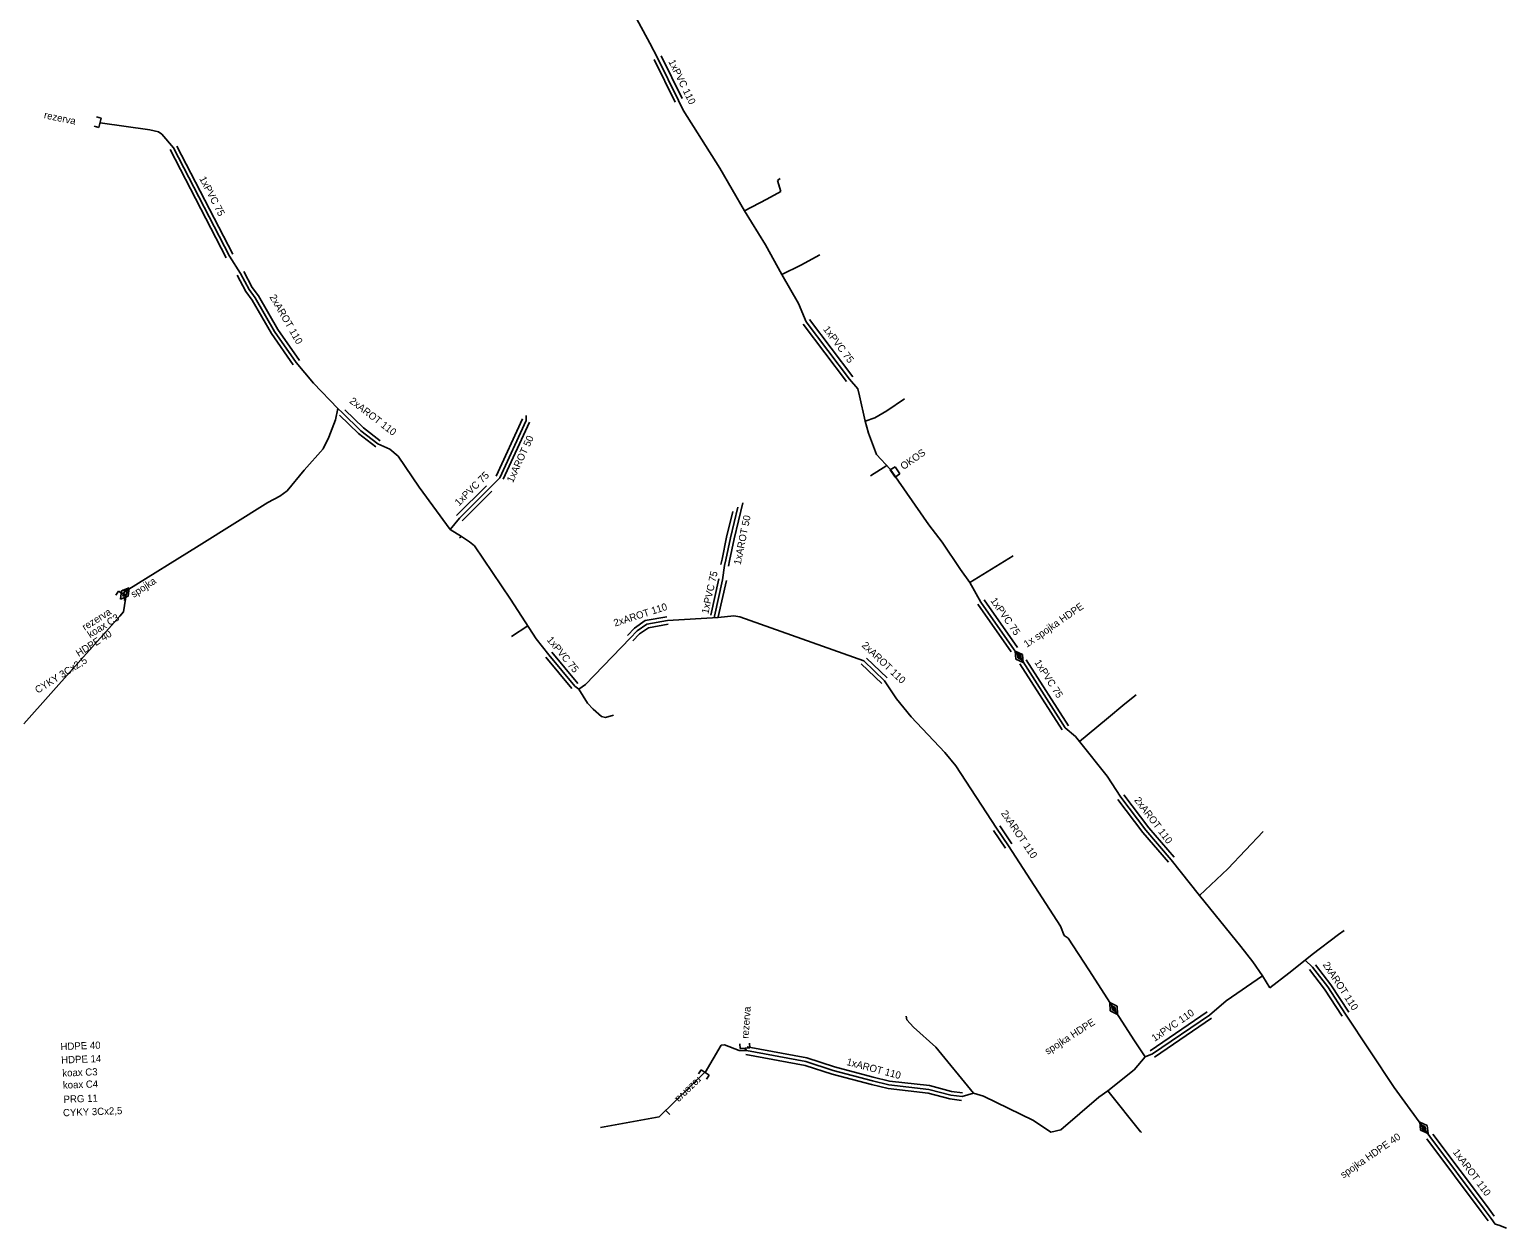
# Model space of a CAD drawing. Extents: x -651943 to -618711, y -1138561 to -1100552.
# Drawn here: x -649090.5 to -648936.6, y -1111816.6 to -1111691.7 of the extents above; entities that cross this region are included whole.
import ezdxf

# ---------------------------------------------------------------- set-up
doc = ezdxf.new("R2010")
doc.units = 0
doc.layers.add('KT trasa', color=7, linetype='Continuous')
doc.layers.add('KT zařízení', color=7, linetype='Continuous')

# ---------------------------------------------------------------- blocks, each defined once
blk = doc.blocks.new('TVREZ')
at = {"layer": 'KT zařízení'}
for p, q in [((-0.05, 0.05), (0, 0.05)), ((0, -0.05), (0, 0.05)), ((-0.05, -0.05), (0, -0.05))]:
    blk.add_line(p, q, dxfattribs=at)
blk = doc.blocks.new('TVSPO_1')
at = {"layer": 'KT zařízení'}
for p, q in [((-0.074, 0.002), (0, 0.044)), ((-0.001, -0.041), (-0.074, 0.002)), ((-0.035, 0), (0, 0.02)), ((0.073, 0.001), (-0.001, -0.041)), ((0, 0.044), (0.073, 0.001)), ((0, 0.02), (0.035, 0)), ((0.035, 0), (0, -0.02)), ((0, -0.02), (-0.035, 0))]:
    blk.add_line(p, q, dxfattribs=at)
blk = doc.blocks.new('POINT_DISPLAY')
blk.add_line((0, 0), (0, 0))

msp = doc.modelspace()

# ---------------------------------------------------------------- linework, layer by layer
at = {"layer": 'KT trasa'}
for p, q in [((-649027.47, -1111690.19), (-649025.84, -1111693.13)), ((-649025.84, -1111693.13), (-649025.05, -1111694.65)), ((-649025.05, -1111694.65), (-649022.86, -1111699.1)), ((-649022.86, -1111699.1), (-649022.39, -1111700.14)), ((-649022.39, -1111700.14), (-649018.57, -1111706.18)), ((-649083.16, -1111701.43), (-649077.98, -1111702.18)), ((-649077.98, -1111702.18), (-649077.08, -1111702.39)), ((-649077.08, -1111702.39), (-649076.72, -1111702.62)), ((-649076.72, -1111702.62), (-649075.51, -1111704.06)), ((-649069.67, -1111715.33), (-649075.51, -1111704.06)), ((-649018.57, -1111706.18), (-649015.98, -1111710.61)), ((-649012.56, -1111707.46), (-649012.27, -1111707.25)), ((-649012.2, -1111708.59), (-649012.56, -1111707.46)), ((-649015.98, -1111710.61), (-649013.67, -1111709.4)), ((-649013.67, -1111709.4), (-649012.2, -1111708.59)), ((-649015.98, -1111710.61), (-649013.81, -1111714.17)), ((-649013.81, -1111714.17), (-649012.08, -1111717.25)), ((-649069.67, -1111715.33), (-649068.53, -1111717.15)), ((-649010.1, -1111716.28), (-649008.14, -1111715.21)), ((-649068.53, -1111717.15), (-649067.63, -1111718.82)), ((-649012.08, -1111717.25), (-649010.1, -1111716.28)), ((-649012.08, -1111717.25), (-649010.37, -1111720.28)), ((-649067.63, -1111718.82), (-649066.98, -1111719.7)), ((-649064.96, -1111723.2), (-649066.98, -1111719.7)), ((-649010.37, -1111720.28), (-649009.55, -1111722.19)), ((-649009.55, -1111722.19), (-649005.03, -1111728.17)), ((-649062.7, -1111726.44), (-649064.96, -1111723.2)), ((-649060.9, -1111728.59), (-649062.7, -1111726.44)), ((-649005.03, -1111728.17), (-649004.16, -1111729.19)), ((-649058.38, -1111731.23), (-649060.9, -1111728.59)), ((-649004.16, -1111729.19), (-649004.01, -1111729.92)), ((-649004.01, -1111729.92), (-649003.4, -1111732.54)), ((-649058.38, -1111731.23), (-649058.63, -1111732.39)), ((-649057.92, -1111731.64), (-649058.38, -1111731.23)), ((-649002.4, -1111732.21), (-649001.14, -1111731.47)), ((-649001.14, -1111731.47), (-648999.31, -1111730.23)), ((-649058.63, -1111732.39), (-649059.3, -1111734.21)), ((-649055.96, -1111733.54), (-649057.92, -1111731.64)), ((-649041.5, -1111738.44), (-649038.75, -1111732.48)), ((-649038.75, -1111732.48), (-649038.73, -1111731.97)), ((-649003.4, -1111732.54), (-649002.4, -1111732.21)), ((-649003.4, -1111732.54), (-649003.07, -1111733.81)), ((-649059.3, -1111734.21), (-649059.91, -1111735.42)), ((-649054.19, -1111734.9), (-649055.96, -1111733.54)), ((-649003.07, -1111733.81), (-649002.23, -1111736.01)), ((-649059.91, -1111735.42), (-649061.9, -1111737.65)), ((-649052.94, -1111735.48), (-649054.19, -1111734.9)), ((-649052.09, -1111736.19), (-649052.94, -1111735.48)), ((-649049.9, -1111739.43), (-649052.09, -1111736.19)), ((-649061.9, -1111737.65), (-649063.65, -1111739.8)), ((-649002.84, -1111738.24), (-649001.16, -1111737.17)), ((-649042.59, -1111739.58), (-649041.5, -1111738.44)), ((-649064.41, -1111740.37), (-649065.68, -1111741.04)), ((-649063.65, -1111739.8), (-649064.41, -1111740.37)), ((-649046.66, -1111743.83), (-649049.9, -1111739.43)), ((-649045.71, -1111742.66), (-649042.59, -1111739.58)), ((-649065.68, -1111741.04), (-649072.81, -1111745.52)), ((-649017.46, -1111744.72), (-649016.68, -1111741.51)), ((-649046.66, -1111743.83), (-649045.71, -1111742.66)), ((-649045.5, -1111744.58), (-649046.66, -1111743.83)), ((-648996.78, -1111743.36), (-648995.39, -1111745.17)), ((-649045.68, -1111744.7), (-649045.5, -1111744.58)), ((-649044.65, -1111745.14), (-649045.5, -1111744.58)), ((-649044.14, -1111745.55), (-649044.65, -1111745.14)), ((-649017.93, -1111747.02), (-649017.46, -1111744.72)), ((-648995.39, -1111745.17), (-648993.47, -1111748.01)), ((-649072.81, -1111745.52), (-649080.42, -1111750.23)), ((-649040.37, -1111751.11), (-649044.14, -1111745.55)), ((-648992.5, -1111749.36), (-648987.97, -1111746.58)), ((-649018.27, -1111749.08), (-649018.06, -1111747.59)), ((-649018.06, -1111747.59), (-649017.93, -1111747.02)), ((-648993.47, -1111748.01), (-648992.5, -1111749.36)), ((-649018.27, -1111749.08), (-649019.11, -1111752.86)), ((-648992.5, -1111749.36), (-648991.35, -1111751.4)), ((-649080.42, -1111750.23), (-649080.85, -1111750.18)), ((-649080.42, -1111750.23), (-649080.81, -1111750.54)), ((-649080.7, -1111752.41), (-649080.52, -1111751.09)), ((-649080.52, -1111751.09), (-649080.56, -1111750.52)), ((-649037.71, -1111755.25), (-649040.37, -1111751.11)), ((-648991.35, -1111751.4), (-648987.87, -1111756.37)), ((-649085.74, -1111758.1), (-649081.1, -1111752.88)), ((-649081.1, -1111752.88), (-649080.7, -1111752.41)), ((-649018.73, -1111753.01), (-649024, -1111753.32)), ((-649019.1, -1111753.03), (-649019.11, -1111752.86)), ((-649017.09, -1111752.85), (-649018.73, -1111753.01)), ((-649016.49, -1111752.94), (-649017.09, -1111752.85)), ((-649003.56, -1111757.55), (-649016.49, -1111752.94)), ((-649038.58, -1111753.9), (-649040.29, -1111755.01)), ((-649027.19, -1111754.42), (-649027.91, -1111755.18)), ((-649026.17, -1111753.71), (-649027.19, -1111754.42)), ((-649024, -1111753.32), (-649026.17, -1111753.71)), ((-649036.38, -1111756.9), (-649037.71, -1111755.25)), ((-649027.91, -1111755.18), (-649032.57, -1111760.01)), ((-649033.67, -1111760.17), (-649036.38, -1111756.9)), ((-649001.39, -1111759.61), (-649003.56, -1111757.55)), ((-648987.87, -1111756.37), (-648986.96, -1111757.64)), ((-648986.96, -1111757.64), (-648982.55, -1111764.52)), ((-649091.11, -1111764.1), (-649085.74, -1111758.1)), ((-649033.27, -1111760.49), (-649033.67, -1111760.17)), ((-649032.57, -1111760.01), (-649033.27, -1111760.49)), ((-649033.27, -1111760.49), (-649032.35, -1111761.95)), ((-649000.13, -1111761.51), (-649001.39, -1111759.61)), ((-649032.35, -1111761.95), (-649031.75, -1111762.57)), ((-648998.62, -1111763.37), (-649000.13, -1111761.51)), ((-648978.24, -1111763.6), (-648976.36, -1111762.02)), ((-648976.36, -1111762.02), (-648975.15, -1111761.08)), ((-649031.75, -1111762.57), (-649030.91, -1111763.35)), ((-649030.91, -1111763.35), (-649030.47, -1111763.43)), ((-649030.47, -1111763.43), (-649029.64, -1111763.19)), ((-648995.11, -1111767.1), (-648998.62, -1111763.37)), ((-648981.08, -1111765.95), (-648978.24, -1111763.6)), ((-648982.55, -1111764.52), (-648981.49, -1111765.41)), ((-648981.49, -1111765.41), (-648981.08, -1111765.95)), ((-648981.08, -1111765.95), (-648978.2, -1111769.56)), ((-648993.97, -1111768.49), (-648995.11, -1111767.1)), ((-648989.72, -1111774.98), (-648993.97, -1111768.49)), ((-648978.2, -1111769.56), (-648976.76, -1111771.75)), ((-648976.76, -1111771.75), (-648974.16, -1111775.18)), ((-648988.46, -1111776.83), (-648989.72, -1111774.98)), ((-648974.16, -1111775.18), (-648971.5, -1111778.27)), ((-648965.62, -1111779.22), (-648961.92, -1111775.33)), ((-648983.04, -1111785.19), (-648988.46, -1111776.83)), ((-648971.5, -1111778.27), (-648968.55, -1111782)), ((-648968.55, -1111782), (-648965.62, -1111779.22)), ((-648968.55, -1111782), (-648964.26, -1111787.33)), ((-648982.67, -1111786.16), (-648983.04, -1111785.19)), ((-648982.25, -1111786.46), (-648982.67, -1111786.16)), ((-648980.09, -1111789.76), (-648982.25, -1111786.46)), ((-648954.06, -1111786.06), (-648956.83, -1111788.15)), ((-648954.06, -1111786.06), (-648953.48, -1111785.64)), ((-648964.26, -1111787.33), (-648963.01, -1111788.91)), ((-648956.83, -1111788.15), (-648957.54, -1111788.73)), ((-648975.34, -1111797.16), (-648980.09, -1111789.76)), ((-648963.01, -1111788.91), (-648961.99, -1111790.36)), ((-648959.25, -1111790.11), (-648957.54, -1111788.73)), ((-648957.54, -1111788.73), (-648956.79, -1111789.48)), ((-648956.79, -1111789.48), (-648955.19, -1111791.53)), ((-648961.99, -1111790.36), (-648965.8, -1111792.99)), ((-648961.99, -1111790.36), (-648961.23, -1111791.64)), ((-648961.23, -1111791.64), (-648959.25, -1111790.11)), ((-648955.19, -1111791.53), (-648953.34, -1111794.37)), ((-648965.8, -1111792.99), (-648967.53, -1111794.47)), ((-648999.06, -1111794.97), (-648999.15, -1111794.58)), ((-648967.53, -1111794.47), (-648973.48, -1111798.51)), ((-648953.34, -1111794.37), (-648948.27, -1111802)), ((-648998.37, -1111795.72), (-648999.06, -1111794.97)), ((-648996.04, -1111797.82), (-648998.37, -1111795.72)), ((-649020.1, -1111800.45), (-649018.43, -1111797.59)), ((-649018.43, -1111797.59), (-649018.06, -1111797.57)), ((-649018.06, -1111797.57), (-649016.53, -1111798.16)), ((-648974.23, -1111798.81), (-648975.34, -1111797.16)), ((-649016.53, -1111798.16), (-649015.77, -1111798.17)), ((-649015.77, -1111798.17), (-649015.94, -1111797.91)), ((-649015.77, -1111798.17), (-649009.58, -1111799.32)), ((-649009.58, -1111799.32), (-649006.74, -1111800.24)), ((-648992.13, -1111802.59), (-648996.04, -1111797.82)), ((-648974.23, -1111798.81), (-648975.39, -1111800.16)), ((-648973.48, -1111798.51), (-648974.23, -1111798.81)), ((-649020.04, -1111800.35), (-649024.88, -1111805.07)), ((-649006.74, -1111800.24), (-649002.66, -1111801.32)), ((-648978.11, -1111802.36), (-648975.39, -1111800.16)), ((-649002.66, -1111801.32), (-649000.94, -1111801.74)), ((-649000.94, -1111801.74), (-648996.79, -1111802.22)), ((-648996.79, -1111802.22), (-648994.49, -1111802.81)), ((-648979.05, -1111803.03), (-648978.11, -1111802.36)), ((-648978.11, -1111802.36), (-648974.68, -1111806.66)), ((-648948.27, -1111802), (-648944.56, -1111807.11)), ((-648994.49, -1111802.81), (-648993.31, -1111802.96)), ((-648993.31, -1111802.96), (-648992.13, -1111802.59)), ((-648992.13, -1111802.59), (-648991.08, -1111802.92)), ((-648991.08, -1111802.92), (-648985.86, -1111805.45)), ((-648983.02, -1111806.43), (-648979.05, -1111803.03)), ((-649024.88, -1111805.07), (-649030.99, -1111806.2)), ((-649023.78, -1111804.83), (-649024.2, -1111804.41)), ((-648985.86, -1111805.45), (-648984.05, -1111806.66)), ((-648984.05, -1111806.66), (-648983.02, -1111806.43)), ((-648974.62, -1111806.62), (-648974.68, -1111806.66)), ((-648944.56, -1111807.11), (-648938.88, -1111814.71)), ((-648938.88, -1111814.71), (-648938.17, -1111815.66)), ((-648938.17, -1111815.66), (-648937.75, -1111816.25)), ((-648937.75, -1111816.25), (-648937.35, -1111816.36)), ((-648937.35, -1111816.36), (-648936.57, -1111816.67))]:
    msp.add_line(p, q, dxfattribs=at)
msp.add_lwpolyline([(-649002.23, -1111736.01), (-649000.81, -1111737.55), (-648996.78, -1111743.36)], dxfattribs=at)
at = {"layer": 'KT zařízení'}
for p, q in [((-649024.69, -1111694.47), (-649022.5, -1111698.92)), ((-649025.41, -1111694.83), (-649023.22, -1111699.28)), ((-649069.31, -1111715.15), (-649075.15, -1111703.88)), ((-649070.03, -1111715.51), (-649075.86, -1111704.24)), ((-649068.88, -1111717.34), (-649067.97, -1111719.03)), ((-649068.18, -1111716.96), (-649067.29, -1111718.61)), ((-649067.97, -1111719.03), (-649067.32, -1111719.92)), ((-649067.29, -1111718.61), (-649066.64, -1111719.48)), ((-649065.3, -1111723.42), (-649067.32, -1111719.92)), ((-649064.62, -1111722.98), (-649066.64, -1111719.48)), ((-649009.23, -1111721.95), (-649004.71, -1111727.93)), ((-649063.03, -1111726.67), (-649065.3, -1111723.42)), ((-649062.37, -1111726.21), (-649064.62, -1111722.98)), ((-649009.87, -1111722.43), (-649005.35, -1111728.41)), ((-649055.7, -1111733.24), (-649057.64, -1111731.35)), ((-649056.22, -1111733.84), (-649058.2, -1111731.93)), ((-649041.86, -1111738.27), (-649039.11, -1111732.31)), ((-649041.14, -1111738.61), (-649038.38, -1111732.64)), ((-649054.43, -1111735.22), (-649056.22, -1111733.84)), ((-649053.95, -1111734.58), (-649055.7, -1111733.24)), ((-649000.79, -1111737.63), (-649000.3, -1111737.29)), ((-649000.79, -1111737.63), (-649000.28, -1111738.37)), ((-649000.3, -1111737.29), (-648999.79, -1111738.03)), ((-649000.28, -1111738.37), (-648999.79, -1111738.03)), ((-649045.99, -1111742.38), (-649042.87, -1111739.3)), ((-649045.43, -1111742.94), (-649042.31, -1111739.86)), ((-649017.85, -1111744.63), (-649017.2, -1111741.98)), ((-649017.07, -1111744.81), (-649016.15, -1111741.05)), ((-649018.32, -1111746.95), (-649017.85, -1111744.63)), ((-649017.54, -1111747.09), (-649017.07, -1111744.81)), ((-649018.45, -1111747.5), (-649018.32, -1111746.95)), ((-649017.67, -1111747.68), (-649017.54, -1111747.09)), ((-649018.66, -1111748.99), (-649019.5, -1111752.77)), ((-649017.88, -1111749.17), (-649018.72, -1111752.95)), ((-648991.02, -1111751.17), (-648987.54, -1111756.14)), ((-649024.07, -1111752.93), (-649026.33, -1111753.33)), ((-648991.68, -1111751.63), (-648988.2, -1111756.6)), ((-649027.45, -1111754.11), (-649028.2, -1111754.9)), ((-649026.33, -1111753.33), (-649027.45, -1111754.11)), ((-649026.01, -1111754.09), (-649026.93, -1111754.72)), ((-649023.93, -1111753.71), (-649026.01, -1111754.09)), ((-649026.93, -1111754.72), (-649027.62, -1111755.46)), ((-649033.98, -1111760.43), (-649036.69, -1111757.16)), ((-649033.36, -1111759.91), (-649036.07, -1111756.64)), ((-649001.11, -1111759.32), (-649003.28, -1111757.26)), ((-648986.62, -1111757.42), (-648982.21, -1111764.3)), ((-649001.67, -1111759.9), (-649003.84, -1111757.84)), ((-648987.3, -1111757.85), (-648982.89, -1111764.74)), ((-648976.44, -1111771.51), (-648973.85, -1111774.93)), ((-648977.08, -1111771.99), (-648974.47, -1111775.43)), ((-648988.79, -1111777.06), (-648990.05, -1111775.21)), ((-648988.13, -1111776.6), (-648989.39, -1111774.75)), ((-648974.47, -1111775.43), (-648971.8, -1111778.53)), ((-648973.85, -1111774.93), (-648971.2, -1111778.01)), ((-648957.1, -1111789.73), (-648955.52, -1111791.76)), ((-648956.47, -1111789.23), (-648954.86, -1111791.3)), ((-648954.86, -1111791.3), (-648953, -1111794.15)), ((-648955.52, -1111791.76), (-648953.68, -1111794.59)), ((-648967.75, -1111794.14), (-648973.7, -1111798.18)), ((-648967.31, -1111794.8), (-648973.26, -1111798.84)), ((-649015.7, -1111797.78), (-649009.48, -1111798.93)), ((-649015.84, -1111798.56), (-649009.68, -1111799.71)), ((-649009.48, -1111798.93), (-649006.62, -1111799.86)), ((-649009.68, -1111799.71), (-649006.86, -1111800.62)), ((-649006.86, -1111800.62), (-649002.76, -1111801.71)), ((-649006.62, -1111799.86), (-649002.56, -1111800.93)), ((-649002.76, -1111801.71), (-649001.01, -1111802.13)), ((-649002.56, -1111800.93), (-649000.87, -1111801.34)), ((-649001.01, -1111802.13), (-648996.86, -1111802.61)), ((-649000.87, -1111801.34), (-648996.72, -1111801.82)), ((-648996.72, -1111801.82), (-648994.41, -1111802.42)), ((-648996.86, -1111802.61), (-648994.57, -1111803.2)), ((-648994.57, -1111803.2), (-648993.36, -1111803.36)), ((-648994.41, -1111802.42), (-648993.26, -1111802.56)), ((-648944.24, -1111806.87), (-648938.56, -1111814.47)), ((-648944.88, -1111807.35), (-648939.2, -1111814.95)), ((-648938.56, -1111814.47), (-648937.85, -1111815.42)), ((-648939.2, -1111814.95), (-648938.49, -1111815.9))]:
    msp.add_line(p, q, dxfattribs=at)

# ---------------------------------------------------------------- block references
at = {"layer": 'KT trasa'}
msp.add_blockref('POINT_DISPLAY', (-649068.53, -1111717.15), dxfattribs=at)
at = {"layer": 'KT zařízení'}
for name, p, xscale, yscale, rotation in [('TVREZ', (-649083.16, -1111701.43), 9.999999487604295, 9.999999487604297, -12.882068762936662), ('TVSPO_1', (-649080.56, -1111750.52), 9.999994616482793, 9.999994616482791, 52.29363940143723), ('TVSPO_1', (-649080.56, -1111750.52), 9.999994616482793, 9.999994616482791, 52.29363940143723), ('TVREZ', (-649080.81, -1111750.54), 9.999982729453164, 9.999982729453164, 58.36827187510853), ('TVSPO_1', (-648987.35, -1111757.1), 10.00000102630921, 10.000001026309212, 126.51061609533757), ('TVSPO_1', (-648977.51, -1111793.79), 10.000018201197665, 10.000018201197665, -56.80010239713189), ('TVREZ', (-649015.94, -1111797.91), 9.999987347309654, 9.999987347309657, -85.91442123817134), ('TVREZ', (-649020.1, -1111800.45), 10.000034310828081, 10.000034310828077, 56.75710729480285), ('TVSPO_1', (-648945.19, -1111806.24), 9.999987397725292, 9.99998739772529, -53.44914948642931)]:
    msp.add_blockref(name, p, dxfattribs=dict(at, xscale=xscale, yscale=yscale, rotation=rotation))

# ---------------------------------------------------------------- texts
for s, rotation, p in [('1xPVC 110', 296.2034, (-649023.94, -1111695.06)), ('rezerva', 348.3012, (-649089.05, -1111700.96)), ('1xPVC 75', 297.3927, (-649072.84, -1111707.25)), ('2xAROT 110', 299.9911, (-649065.53, -1111719.59)), ('1xPVC 75', 307.0839, (-649007.83, -1111722.97)), ('2xAROT 110', 322.4552, (-649057.23, -1111730.58)), ('1xAROT 50', 65.2218, (-649040.13, -1111739.02)), ('OKOS', 34.9475, (-648999.41, -1111737.65)), ('1xPVC 75', 44.6304, (-649045.75, -1111741.44)), ('1xAROT 50', 78.4431, (-649016.39, -1111747.57)), ('1xPVC 75', 77.4712, (-649019.76, -1111752.68)), ('spojka', 33.2763, (-649079.65, -1111750.98)), ('spojka', 33.2763, (-649079.65, -1111750.98)), ('2xAROT 110', 17.8307, (-649029.49, -1111753.97)), ('1xPVC 75', 304.9998, (-648990.39, -1111751.26)), ('1x spojka HDPE', 34.7186, (-648986.56, -1111756.18)), ('rezerva', 32.2337, (-649084.74, -1111754.41)), ('koax C3', 32.2337, (-649084.19, -1111755.18)), ('HDPE 40', 32.2337, (-649085.39, -1111757.14)), ('1xPVC 75', 309.6501, (-649036.64, -1111755.37)), ('2xAROT 110', 316.4896, (-649003.83, -1111755.99)), ('CYKY 3Cx2,5', 32.2337, (-649089.65, -1111760.97)), ('1xPVC 75', 302.6594, (-648985.8, -1111757.7)), ('2xAROT 110', 304.258, (-648989.29, -1111773.43)), ('2xAROT 110', 307.1612, (-648975.41, -1111772.07)), ('2xAROT 110', 303.0789, (-648955.75, -1111789.2)), ('rezerva', 86.0371, (-649015.57, -1111796.94)), ('1xPVC 110', 34.1762, (-648973.24, -1111797.26)), ('spojka HDPE', 32.6961, (-648984.39, -1111798.62)), ('HDPE 40', 2.1409, (-649087.27, -1111798.12)), ('HDPE 40', 2.1409, (-649087.27, -1111798.12)), ('HDPE 14', 2.1409, (-649087.2, -1111799.52)), ('HDPE 14', 2.1409, (-649087.2, -1111799.52)), ('1xAROT 110', 345.1836, (-649005.41, -1111799.66)), ('koax C3', 2.1409, (-649087.08, -1111800.88)), ('koax C3', 2.1409, (-649087.08, -1111800.88)), ('koax C4', 2.1409, (-649087.02, -1111802.14)), ('koax C4', 2.1409, (-649087.02, -1111802.14)), ('rezerva', 223.7096, (-649020.85, -1111800.85)), ('PRG 11', 2.1409, (-649086.95, -1111803.62)), ('PRG 11', 2.1409, (-649086.95, -1111803.62)), ('CYKY 3Cx2,5', 2.1409, (-649087.01, -1111805.02)), ('CYKY 3Cx2,5', 2.1409, (-649087.01, -1111805.02)), ('spojka HDPE 40', 34.6974, (-648953.57, -1111811.51)), ('1xAROT 110', 306.7733, (-648942.2, -1111808.77))]:
    msp.add_text(s, height=0.75, rotation=rotation, dxfattribs=at).set_placement(p)

doc.saveas('drawing.dxf')
